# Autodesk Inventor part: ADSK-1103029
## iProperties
Shininess: 50.0
Length Units: 11272
Angle Units: 11279
Time Units: 11290
Mass Units: 11286
Length Display Precision: 4
Angle Display Precision: 2
Compacted: True
Created: 2000-08
Part Number: ADSK-1103029
Document SubType Name: Modeling
Description: CLUTCH NUT
Mass: 2.21466 g
Surface Area: 6.28565 cm^2
Volume: 0.491055 cm^3
Density: 4.51 g/cm^3
Material: Titanium
Density: 0.0
Volumn: 0.0
Area: 0.0
PropertySet Name: Model Information
Control State: 0
Master: False
Checked Out: False
Author: Autodesk, Inc.
